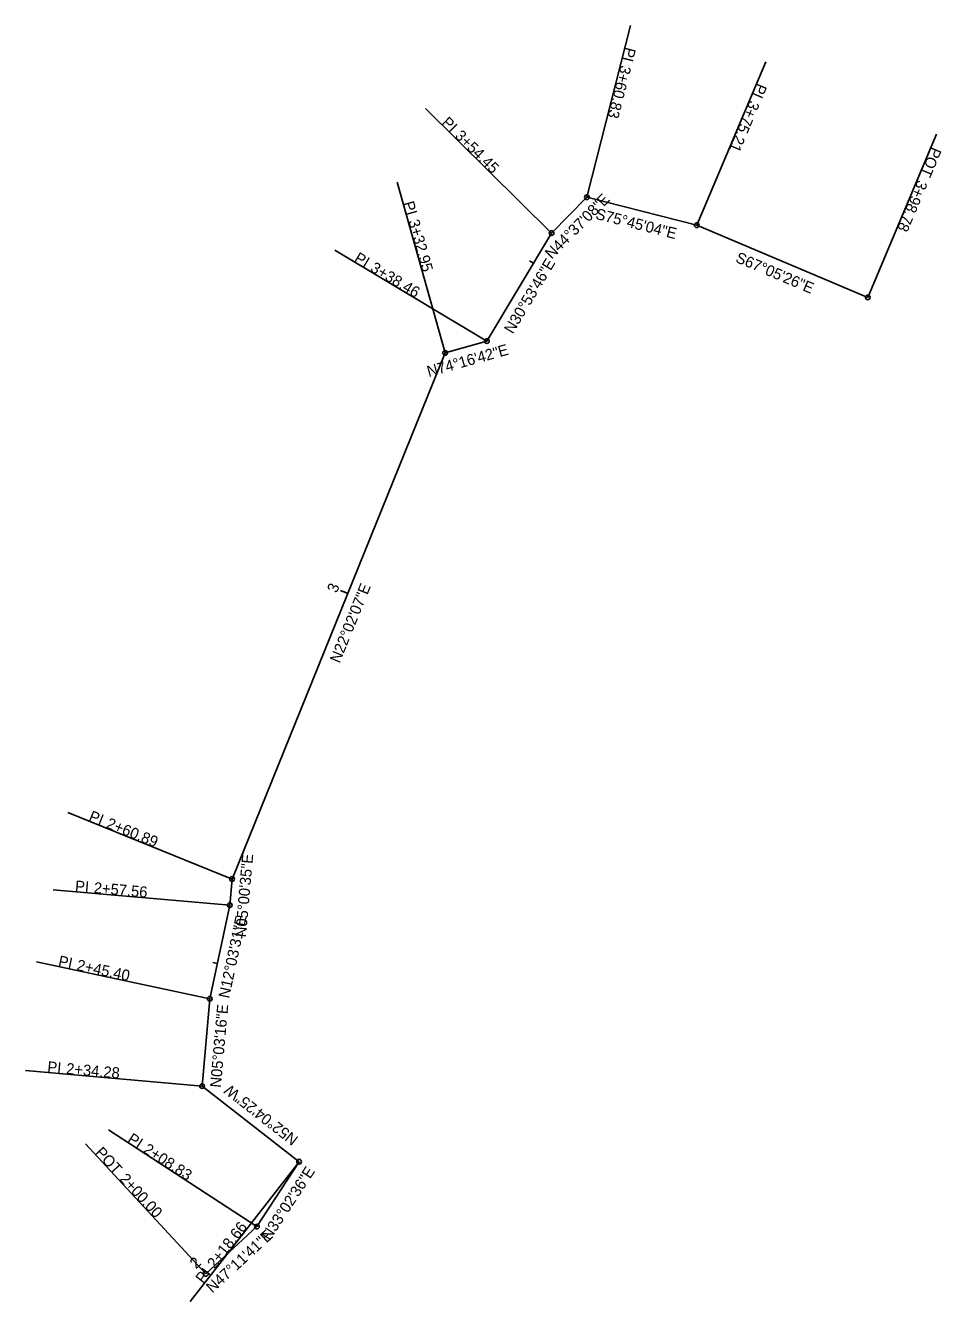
# Model space of a CAD drawing. Extents: x 2347208 to 2347745, y 627099 to 627583.
# Drawn here: x 2347208.1 to 2347324.3, y 627421.4 to 627583.4 of the extents above; entities that cross this region are included whole.
import ezdxf

# ---------------------------------------------------------------- set-up
doc = ezdxf.new("R2010")
doc.units = 0
for name, color, linetype in [('DR_X_Culvert', 7, 'Continuous'), ('DR_X_Text', 7, 'Continuous'), ('DT_X_Contour_Minor', 7, 'Continuous'), ('DT_X_TIN_Hull', 7, 'Continuous'), ('SV_X_Terrain_Boundary', 7, 'Continuous'), ('SV_X_Terrain_Break_Line', 7, 'Continuous'), ('SV_X_Toe_of_Slope', 7, 'Continuous'), ('SV_X_Top_of_Bank', 7, 'Continuous'), ('VG_X_Text', 7, 'Continuous')]:
    doc.layers.add(name, color=color, linetype=linetype)

msp = doc.modelspace()

# ---------------------------------------------------------------- linework, layer by layer
at = {"layer": 'DR_X_Culvert'}
for p, q in [((2347279.31, 627561.57), (2347284.85, 627583.38)), ((2347293.25, 627558.03), (2347302.01, 627578.76)), ((2347274.83, 627557.03), (2347258.81, 627572.83)), ((2347314.96, 627548.86), (2347323.71, 627569.58)), ((2347261.32, 627541.82), (2347255.22, 627563.48)), ((2347266.62, 627543.31), (2347247.31, 627554.86)), ((2347234.28, 627475.02), (2347213.42, 627483.46)), ((2347233.99, 627471.7), (2347211.58, 627473.66)), ((2347231.45, 627459.81), (2347209.45, 627464.51)), ((2347230.47, 627448.73), (2347208.06, 627450.71)), ((2347237.43, 627430.89), (2347218.57, 627443.16)), ((2347230.95, 627424.89), (2347215.66, 627441.4)), ((2347242.79, 627439.13), (2347228.96, 627421.38))]:
    msp.add_line(p, q, dxfattribs=at)
for centre in [(2347279.31, 627561.57), (2347274.83, 627557.03), (2347293.25, 627558.03), (2347314.96, 627548.86), (2347266.62, 627543.31), (2347261.32, 627541.82), (2347234.28, 627475.02), (2347233.99, 627471.7), (2347231.45, 627459.81), (2347230.47, 627448.73), (2347242.79, 627439.13), (2347237.43, 627430.89), (2347230.95, 627424.89)]:
    msp.add_circle(centre, 0.3, dxfattribs=at)
at = {"layer": 'DT_X_Contour_Minor'}
for p, q in [((2347274.83, 627557.03), (2347279.31, 627561.57)), ((2347279.31, 627561.57), (2347293.25, 627558.03)), ((2347293.25, 627558.03), (2347314.96, 627548.86)), ((2347266.62, 627543.31), (2347274.83, 627557.03)), ((2347261.32, 627541.82), (2347266.62, 627543.31)), ((2347234.28, 627475.02), (2347261.32, 627541.82)), ((2347233.99, 627471.7), (2347234.28, 627475.02)), ((2347231.45, 627459.81), (2347233.99, 627471.7)), ((2347230.47, 627448.73), (2347231.45, 627459.81)), ((2347242.79, 627439.13), (2347230.47, 627448.73)), ((2347237.43, 627430.89), (2347242.79, 627439.13)), ((2347230.95, 627424.89), (2347237.43, 627430.89))]:
    msp.add_line(p, q, dxfattribs=at)
at = {"layer": 'SV_X_Terrain_Boundary'}
for p, q in [((2347279.31, 627561.57), (2347284.85, 627583.38)), ((2347293.25, 627558.03), (2347302.01, 627578.76)), ((2347274.83, 627557.03), (2347258.81, 627572.83)), ((2347314.96, 627548.86), (2347323.71, 627569.58)), ((2347261.32, 627541.82), (2347255.22, 627563.48)), ((2347266.62, 627543.31), (2347247.31, 627554.86)), ((2347234.28, 627475.02), (2347213.42, 627483.46)), ((2347233.99, 627471.7), (2347211.58, 627473.66)), ((2347231.45, 627459.81), (2347209.45, 627464.51)), ((2347230.47, 627448.73), (2347208.06, 627450.71)), ((2347237.43, 627430.89), (2347218.57, 627443.16)), ((2347230.95, 627424.89), (2347215.66, 627441.4)), ((2347242.79, 627439.13), (2347228.96, 627421.38))]:
    msp.add_line(p, q, dxfattribs=at)
for centre in [(2347279.31, 627561.57), (2347274.83, 627557.03), (2347293.25, 627558.03), (2347314.96, 627548.86), (2347266.62, 627543.31), (2347261.32, 627541.82), (2347234.28, 627475.02), (2347233.99, 627471.7), (2347231.45, 627459.81), (2347230.47, 627448.73), (2347242.79, 627439.13), (2347237.43, 627430.89), (2347230.95, 627424.89)]:
    msp.add_circle(centre, 0.3, dxfattribs=at)
at = {"layer": 'SV_X_Toe_of_Slope'}
for p, q in [((2347248.95, 627511.27), (2347248.4, 627511.5)), ((2347230.95, 627424.89), (2347230.55, 627425.33))]:
    msp.add_line(p, q, dxfattribs=at)
at = {"layer": 'SV_X_Top_of_Bank'}
for p, q in [((2347272.54, 627553.21), (2347272.03, 627553.52)), ((2347248.95, 627511.27), (2347248.03, 627511.65)), ((2347232.41, 627464.31), (2347231.82, 627464.43)), ((2347230.95, 627424.89), (2347230.27, 627425.63))]:
    msp.add_line(p, q, dxfattribs=at)
at = {"layer": 'VG_X_Text'}
for p, q in [((2347279.31, 627561.57), (2347284.85, 627583.38)), ((2347293.25, 627558.03), (2347302.01, 627578.76)), ((2347274.83, 627557.03), (2347258.81, 627572.83)), ((2347314.96, 627548.86), (2347323.71, 627569.58)), ((2347261.32, 627541.82), (2347255.22, 627563.48)), ((2347266.62, 627543.31), (2347247.31, 627554.86)), ((2347234.28, 627475.02), (2347213.42, 627483.46)), ((2347233.99, 627471.7), (2347211.58, 627473.66)), ((2347231.45, 627459.81), (2347209.45, 627464.51)), ((2347230.47, 627448.73), (2347208.06, 627450.71)), ((2347237.43, 627430.89), (2347218.57, 627443.16)), ((2347230.95, 627424.89), (2347215.66, 627441.4)), ((2347242.79, 627439.13), (2347228.96, 627421.38))]:
    msp.add_line(p, q, dxfattribs=at)
for centre in [(2347279.31, 627561.57), (2347274.83, 627557.03), (2347293.25, 627558.03), (2347314.96, 627548.86), (2347266.62, 627543.31), (2347261.32, 627541.82), (2347234.28, 627475.02), (2347233.99, 627471.7), (2347231.45, 627459.81), (2347230.47, 627448.73), (2347242.79, 627439.13), (2347237.43, 627430.89), (2347230.95, 627424.89)]:
    msp.add_circle(centre, 0.3, dxfattribs=at)

# ---------------------------------------------------------------- texts
at = {"layer": 'DR_X_Culvert'}
for s, rotation, p in [('PI', 255.7512, (2347284.2, 627580.71)), ('3+60.83', 255.7512, (2347283.61, 627578.4)), ('PI', 247.0904, (2347300.93, 627576.15)), ('3+75.21', 247.0904, (2347300, 627573.95)), ('PI', 315.3811, (2347260.77, 627570.93)), ('3+54.45', 315.3811, (2347262.47, 627569.26)), ('POT', 247.0904, (2347323.09, 627568.05)), ('3+98.78', 247.0904, (2347321.32, 627563.85)), ('PI', 285.7216, (2347255.98, 627560.86)), ('3+32.95', 285.7216, (2347256.63, 627558.55)), ('PI', 329.1038, (2347249.67, 627553.48)), ('3+38.46', 329.1038, (2347251.72, 627552.25)), ('PI', 337.9647, (2347215.98, 627482.46)), ('2+60.89', 337.9647, (2347218.2, 627481.56)), ('PI', 354.9903, (2347214.3, 627473.45)), ('2+57.56', 354.9903, (2347216.68, 627473.24)), ('PI', 347.9414, (2347212.13, 627463.96)), ('2+45.40', 347.9414, (2347214.46, 627463.46)), ('PI', 354.9455, (2347210.78, 627450.49)), ('2+34.28', 354.9455, (2347213.17, 627450.28)), ('PI', 326.9566, (2347220.88, 627441.68)), ('POT', 312.8052, (2347216.8, 627440.21)), ('2+08.83', 326.9566, (2347222.89, 627440.38)), ('2+00.00', 312.8052, (2347219.9, 627436.86)), ('2+18.66', 52.0735, (2347232.09, 627425.44)), ('PI', 52.0735, (2347230.62, 627423.55))]:
    msp.add_text(s, height=1.4, rotation=rotation, dxfattribs=at).set_placement(p)
at = {"layer": 'DR_X_Text'}
for s, rotation, p in [('N44°37\'08"E', 45.3811, (2347274.85, 627553.64)), ('S75°45\'04"E', 345.7512, (2347280.32, 627558.84)), ('S67°05\'26"E', 337.0904, (2347298.07, 627553.39)), ('N30°53\'46"E', 59.1038, (2347269.91, 627544.14)), ('N74°16\'42"E', 15.7216, (2347259.24, 627538.74)), ('N22°02\'07"E', 67.9647, (2347247.93, 627502.34)), ('N05°00\'35"E', 84.9903, (2347236.04, 627467.58)), ('N12°03\'31"E', 77.9414, (2347233.9, 627459.79)), ('N05°03\'16"E', 84.9455, (2347232.86, 627448.49)), ('N52°04\'25"W', 142.0735, (2347242.78, 627442.18)), ('N33°02\'36"E', 56.9566, (2347239.07, 627429.02)), ('N47°11\'41"E', 42.8052, (2347231.77, 627422.38))]:
    msp.add_text(s, height=1.4, rotation=rotation, dxfattribs=at).set_placement(p)
at = {"layer": 'DT_X_TIN_Hull'}
for s, rotation, p in [('N44°37\'08"E', 45.3811, (2347274.85, 627553.64)), ('S75°45\'04"E', 345.7512, (2347280.32, 627558.84)), ('S67°05\'26"E', 337.0904, (2347298.07, 627553.39)), ('N30°53\'46"E', 59.1038, (2347269.91, 627544.14)), ('N74°16\'42"E', 15.7216, (2347259.24, 627538.74)), ('N22°02\'07"E', 67.9647, (2347247.93, 627502.34)), ('N05°00\'35"E', 84.9903, (2347236.04, 627467.58)), ('N12°03\'31"E', 77.9414, (2347233.9, 627459.79)), ('N05°03\'16"E', 84.9455, (2347232.86, 627448.49)), ('N52°04\'25"W', 142.0735, (2347242.78, 627442.18)), ('N33°02\'36"E', 56.9566, (2347239.07, 627429.02)), ('N47°11\'41"E', 42.8052, (2347231.77, 627422.38))]:
    msp.add_text(s, height=1.4, rotation=rotation, dxfattribs=at).set_placement(p)
at = {"layer": 'SV_X_Terrain_Boundary'}
for s, rotation, p in [('PI', 255.7512, (2347284.2, 627580.71)), ('3+60.83', 255.7512, (2347283.61, 627578.4)), ('PI', 247.0904, (2347300.93, 627576.15)), ('3+75.21', 247.0904, (2347300, 627573.95)), ('PI', 315.3811, (2347260.77, 627570.93)), ('3+54.45', 315.3811, (2347262.47, 627569.26)), ('POT', 247.0904, (2347323.09, 627568.05)), ('3+98.78', 247.0904, (2347321.32, 627563.85)), ('PI', 285.7216, (2347255.98, 627560.86)), ('3+32.95', 285.7216, (2347256.63, 627558.55)), ('PI', 329.1038, (2347249.67, 627553.48)), ('3+38.46', 329.1038, (2347251.72, 627552.25)), ('PI', 337.9647, (2347215.98, 627482.46)), ('2+60.89', 337.9647, (2347218.2, 627481.56)), ('PI', 354.9903, (2347214.3, 627473.45)), ('2+57.56', 354.9903, (2347216.68, 627473.24)), ('PI', 347.9414, (2347212.13, 627463.96)), ('2+45.40', 347.9414, (2347214.46, 627463.46)), ('PI', 354.9455, (2347210.78, 627450.49)), ('2+34.28', 354.9455, (2347213.17, 627450.28)), ('PI', 326.9566, (2347220.88, 627441.68)), ('POT', 312.8052, (2347216.8, 627440.21)), ('2+08.83', 326.9566, (2347222.89, 627440.38)), ('2+00.00', 312.8052, (2347219.9, 627436.86)), ('2+18.66', 52.0735, (2347232.09, 627425.44)), ('PI', 52.0735, (2347230.62, 627423.55))]:
    msp.add_text(s, height=1.4, rotation=rotation, dxfattribs=at).set_placement(p)
at = {"layer": 'SV_X_Terrain_Break_Line'}
for s, rotation, p in [('N44°37\'08"E', 45.3811, (2347274.85, 627553.64)), ('S75°45\'04"E', 345.7512, (2347280.32, 627558.84)), ('S67°05\'26"E', 337.0904, (2347298.07, 627553.39)), ('N30°53\'46"E', 59.1038, (2347269.91, 627544.14)), ('N74°16\'42"E', 15.7216, (2347259.24, 627538.74)), ('N22°02\'07"E', 67.9647, (2347247.93, 627502.34)), ('N05°00\'35"E', 84.9903, (2347236.04, 627467.58)), ('N12°03\'31"E', 77.9414, (2347233.9, 627459.79)), ('N05°03\'16"E', 84.9455, (2347232.86, 627448.49)), ('N52°04\'25"W', 142.0735, (2347242.78, 627442.18)), ('N33°02\'36"E', 56.9566, (2347239.07, 627429.02)), ('N47°11\'41"E', 42.8052, (2347231.77, 627422.38))]:
    msp.add_text(s, height=1.4, rotation=rotation, dxfattribs=at).set_placement(p)
at = {"layer": 'SV_X_Top_of_Bank'}
for s, rotation, p in [('3', 67.9647, (2347247.57, 627511.25)), ('2', 42.8052, (2347229.7, 627425.44))]:
    msp.add_text(s, height=1.4, rotation=rotation, dxfattribs=at).set_placement(p)
at = {"layer": 'VG_X_Text'}
for s, rotation, p in [('PI', 255.7512, (2347284.2, 627580.71)), ('3+60.83', 255.7512, (2347283.61, 627578.4)), ('PI', 247.0904, (2347300.93, 627576.15)), ('3+75.21', 247.0904, (2347300, 627573.95)), ('PI', 315.3811, (2347260.77, 627570.93)), ('3+54.45', 315.3811, (2347262.47, 627569.26)), ('POT', 247.0904, (2347323.09, 627568.05)), ('3+98.78', 247.0904, (2347321.32, 627563.85)), ('PI', 285.7216, (2347255.98, 627560.86)), ('3+32.95', 285.7216, (2347256.63, 627558.55)), ('PI', 329.1038, (2347249.67, 627553.48)), ('3+38.46', 329.1038, (2347251.72, 627552.25)), ('PI', 337.9647, (2347215.98, 627482.46)), ('2+60.89', 337.9647, (2347218.2, 627481.56)), ('PI', 354.9903, (2347214.3, 627473.45)), ('2+57.56', 354.9903, (2347216.68, 627473.24)), ('PI', 347.9414, (2347212.13, 627463.96)), ('2+45.40', 347.9414, (2347214.46, 627463.46)), ('PI', 354.9455, (2347210.78, 627450.49)), ('2+34.28', 354.9455, (2347213.17, 627450.28)), ('PI', 326.9566, (2347220.88, 627441.68)), ('POT', 312.8052, (2347216.8, 627440.21)), ('2+08.83', 326.9566, (2347222.89, 627440.38)), ('2+00.00', 312.8052, (2347219.9, 627436.86)), ('2+18.66', 52.0735, (2347232.09, 627425.44)), ('PI', 52.0735, (2347230.62, 627423.55))]:
    msp.add_text(s, height=1.4, rotation=rotation, dxfattribs=at).set_placement(p)

doc.saveas('drawing.dxf')
